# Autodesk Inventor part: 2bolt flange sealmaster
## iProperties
Author: rmjbm2
Shininess: 20.0
PropertySet Name: _Private Model Information
Created: 2001-06
Part Number: 2bolt flange sealmaster
Document SubType Name: Modeling
Designer: rmjbm2
Control State: 0
Master: False
Checked Out: False
PropertySet Name: Design Tracking Control
Density: 0.0
Volumn: 0.0
Area: 0.0
PropertySet Name: Model Information
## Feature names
1. Extrusion1
2. Extrusion2
3. Extrusion3
4. Extrusion4
5. Extrusion5
6. Hole1
7. Fillet1
8. Fillet2
9. Fillet3
10. Hole2
11. Circular Pattern1
12. Revolution1
